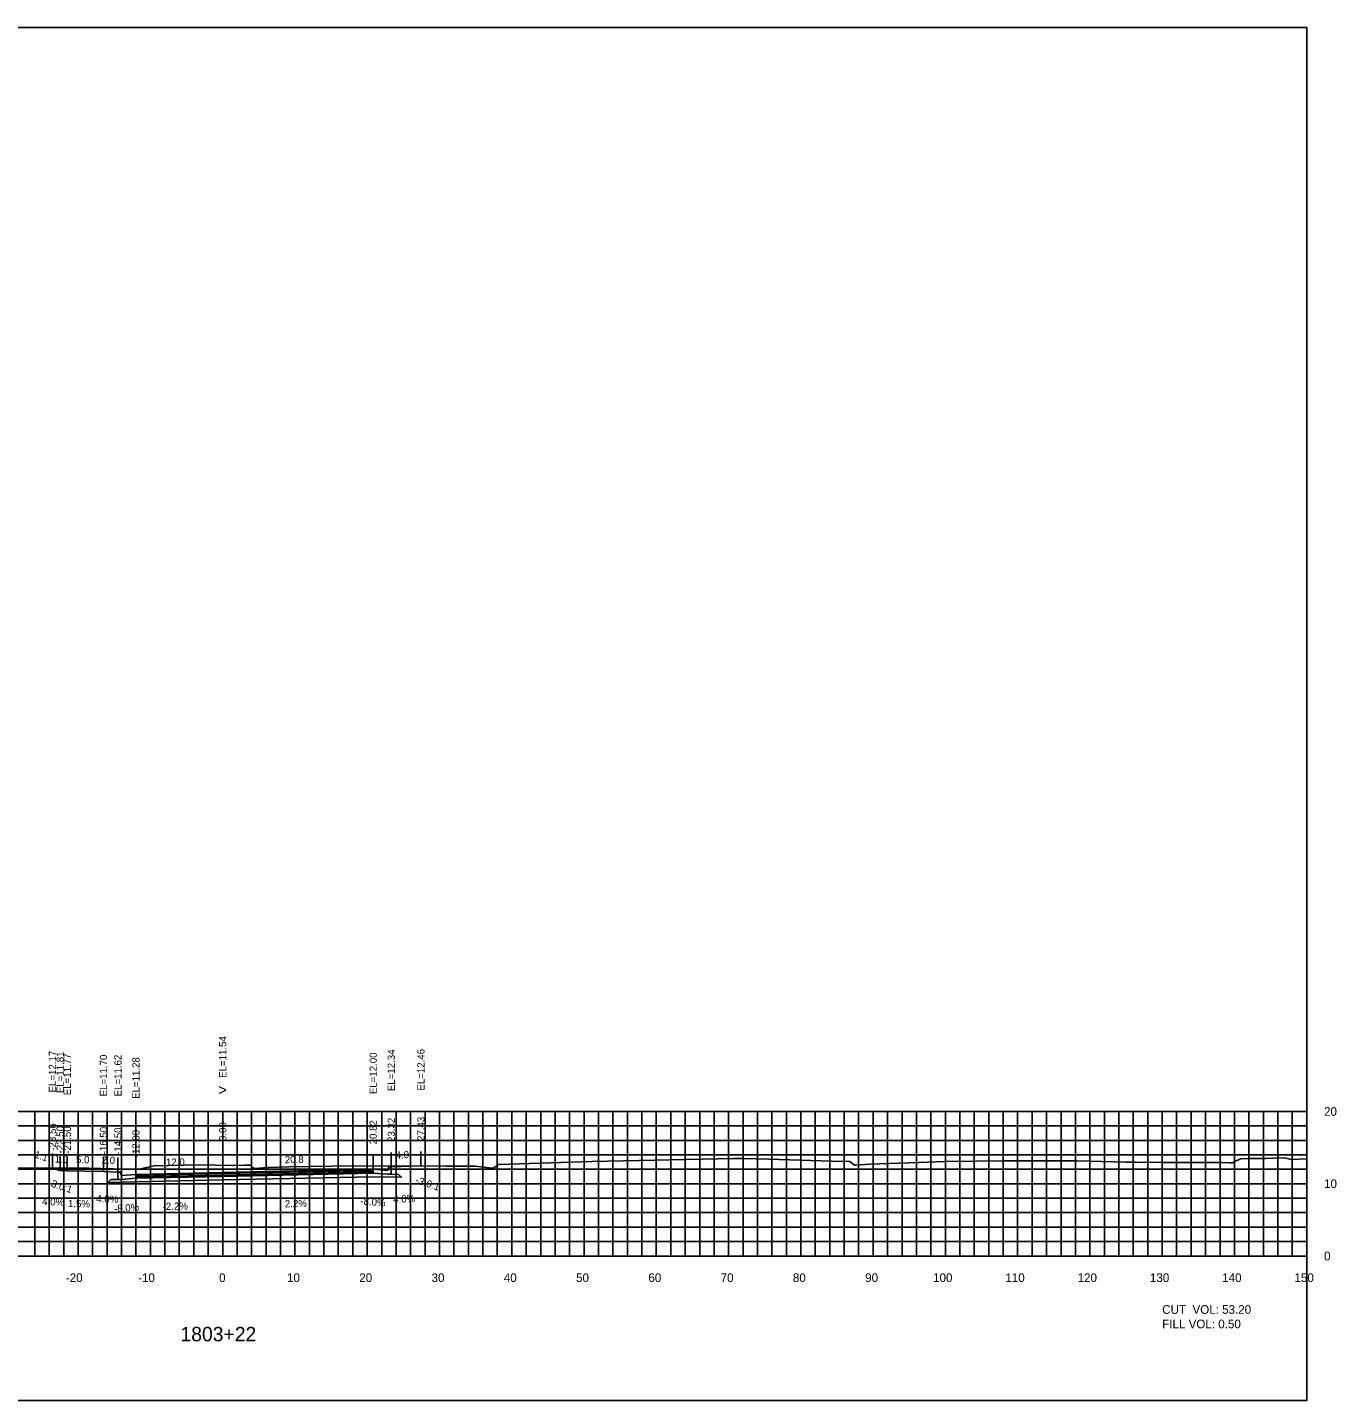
# Model space of a CAD drawing. Extents: x 1797759 to 1802785, y 249826 to 250371.
# Drawn here: x 1802604 to 1802785.1, y 250079.4 to 250269.4 of the extents above; entities that cross this region are included whole.
import ezdxf

# ---------------------------------------------------------------- set-up
doc = ezdxf.new("R2010")
doc.units = 0
for name, color, linetype in [('29', 7, 'Continuous'), ('AXIS', 7, 'Continuous'), ('great seal', 7, 'Continuous'), ('Level 1', 7, 'Continuous'), ('Level 10', 7, 'Continuous'), ('Level 13', 7, 'Continuous'), ('Level 15', 7, 'Continuous'), ('Level 30', 7, 'Continuous'), ('Level 40', 7, 'Continuous'), ('Level 45', 7, 'Continuous'), ('Level 63', 7, 'Continuous'), ('Level 7', 7, 'Continuous'), ('LS-SURVEY POINT', 7, 'Continuous'), ('PIPE', 7, 'Continuous'), ('TOPO', 7, 'Continuous')]:
    doc.layers.add(name, color=color, linetype=linetype)

msp = doc.modelspace()

# ---------------------------------------------------------------- linework, layer by layer
at = {"layer": '29'}
msp.add_lwpolyline([(1802619, 250110.56), (1802631, 250110.83), (1802651.82, 250111.28), (1802651.82, 250111.09), (1802631, 250110.64), (1802619, 250110.37)], close=True, dxfattribs=at)
at = {"layer": 'AXIS'}
for p, q in [((1802607.44, 250111.6), (1802607.44, 250113.6)), ((1802608.5, 250111.25), (1802608.5, 250113.25)), ((1802609.5, 250111.21), (1802609.5, 250113.21)), ((1802614.5, 250111.13), (1802614.5, 250113.13)), ((1802616.5, 250111.05), (1802616.5, 250113.05)), ((1802619, 250110.71), (1802619, 250112.71)), ((1802631, 250110.98), (1802631, 250112.98)), ((1802651.82, 250111.43), (1802651.82, 250113.43)), ((1802654.32, 250111.77), (1802654.32, 250113.77)), ((1802658.43, 250111.9), (1802658.43, 250113.9))]:
    msp.add_line(p, q, dxfattribs=at)
for points in [[(1802481, 250079.43), (1802781, 250079.43), (1802781, 250269.43), (1802481, 250269.43)], [(1802619, 250110.71), (1802617, 250110.55), (1802616.83, 250111.05), (1802616.5, 250111.05), (1802616.5, 250110.02), (1802617, 250110.02), (1802619, 250110.18)], [(1802651.82, 250111.43), (1802653.82, 250111.27), (1802653.99, 250111.77), (1802654.32, 250111.77), (1802654.32, 250110.74), (1802653.82, 250110.74), (1802651.82, 250110.9)]]:
    msp.add_lwpolyline(points, close=True, dxfattribs=at)
at = {"layer": 'great seal'}
msp.add_lwpolyline([(1802588.48, 250111.61), (1802612.48, 250111.6), (1802617.52, 250111.45), (1802619.18, 250111.4), (1802619.69, 250111.51), (1802621.49, 250111.89), (1802627.66, 250112.03), (1802632.32, 250111.95), (1802634.01, 250111.98), (1802634.3, 250111.98), (1802634.8, 250111.99), (1802635.2, 250111.65), (1802635.36, 250111.52), (1802636.61, 250111.65), (1802636.99, 250111.69), (1802637.36, 250111.7), (1802640.13, 250111.75), (1802649.16, 250111.93), (1802661.91, 250111.88), (1802665.94, 250111.87), (1802667.52, 250111.7), (1802668.44, 250111.6), (1802668.65, 250111.74), (1802669.16, 250112.08), (1802682.1, 250112.52), (1802701.74, 250112.94), (1802703.07, 250112.91), (1802706.59, 250112.81), (1802715.25, 250112.57), (1802717.76, 250112.5), (1802718.38, 250112.04), (1802718.43, 250112), (1802718.62, 250112.02), (1802720.55, 250112.12), (1802727.27, 250112.37), (1802730.98, 250112.49), (1802735.32, 250112.56), (1802739.15, 250112.61), (1802743.91, 250112.61), (1802749.17, 250112.62), (1802756.04, 250112.43), (1802757.31, 250112.42), (1802760.91, 250112.39), (1802768.04, 250112.38), (1802768.3, 250112.37), (1802769.24, 250112.36), (1802770.38, 250112.34), (1802770.75, 250112.33), (1802770.94, 250112.44), (1802771.82, 250112.88), (1802773.1, 250112.91), (1802775.32, 250112.93), (1802776.31, 250112.96), (1802777.93, 250113.01), (1802778.84, 250112.8), (1802781, 250112.9)], dxfattribs=at)
at = {"layer": 'Level 1'}
msp.add_lwpolyline([(1802607.44, 250111.6), (1802608.5, 250111.25), (1802609.5, 250111.21), (1802614.5, 250111.13), (1802616.5, 250111.05), (1802616.83, 250111.05), (1802617, 250110.55), (1802619, 250110.71), (1802631, 250110.98), (1802651.82, 250111.43), (1802653.82, 250111.27), (1802653.99, 250111.77), (1802654.32, 250111.77), (1802658.32, 250111.93), (1802658.43, 250111.9)], dxfattribs=at)
at = {"layer": 'Level 13'}
msp.add_lwpolyline([(1802651.82, 250110.4), (1802655.72, 250110.32), (1802655.32, 250110.72), (1802654.32, 250110.74), (1802653.82, 250110.74), (1802651.82, 250110.9), (1802631, 250110.45), (1802619, 250110.18), (1802617, 250110.02), (1802616.5, 250110.02), (1802615.5, 250110), (1802615.1, 250109.6), (1802619, 250109.68), (1802631, 250109.95)], close=True, dxfattribs=at)
at = {"layer": 'Level 15'}
for p, q in [((1802481, 250119.43), (1802781, 250119.43)), ((1802605, 250099.43), (1802605, 250119.43)), ((1802607, 250099.43), (1802607, 250119.43)), ((1802609, 250099.43), (1802609, 250119.43)), ((1802611, 250099.43), (1802611, 250119.43)), ((1802613, 250099.43), (1802613, 250119.43)), ((1802615, 250099.43), (1802615, 250119.43)), ((1802617, 250099.43), (1802617, 250119.43)), ((1802619, 250099.43), (1802619, 250119.43)), ((1802621, 250099.43), (1802621, 250119.43)), ((1802623, 250099.43), (1802623, 250119.43)), ((1802625, 250099.43), (1802625, 250119.43)), ((1802627, 250099.43), (1802627, 250119.43)), ((1802629, 250099.43), (1802629, 250119.43)), ((1802631, 250099.43), (1802631, 250119.43)), ((1802633, 250099.43), (1802633, 250119.43)), ((1802635, 250099.43), (1802635, 250119.43)), ((1802637, 250099.43), (1802637, 250119.43)), ((1802639, 250099.43), (1802639, 250119.43)), ((1802641, 250099.43), (1802641, 250119.43)), ((1802643, 250099.43), (1802643, 250119.43)), ((1802645, 250099.43), (1802645, 250119.43)), ((1802647, 250099.43), (1802647, 250119.43)), ((1802649, 250099.43), (1802649, 250119.43)), ((1802651, 250099.43), (1802651, 250119.43)), ((1802653, 250099.43), (1802653, 250119.43)), ((1802655, 250099.43), (1802655, 250119.43)), ((1802657, 250099.43), (1802657, 250119.43)), ((1802659, 250099.43), (1802659, 250119.43)), ((1802661, 250099.43), (1802661, 250119.43)), ((1802663, 250099.43), (1802663, 250119.43)), ((1802665, 250099.43), (1802665, 250119.43)), ((1802667, 250099.43), (1802667, 250119.43)), ((1802669, 250099.43), (1802669, 250119.43)), ((1802671, 250099.43), (1802671, 250119.43)), ((1802673, 250099.43), (1802673, 250119.43)), ((1802675, 250099.43), (1802675, 250119.43)), ((1802677, 250099.43), (1802677, 250119.43)), ((1802679, 250099.43), (1802679, 250119.43)), ((1802681, 250099.43), (1802681, 250119.43)), ((1802683, 250099.43), (1802683, 250119.43)), ((1802685, 250099.43), (1802685, 250119.43)), ((1802687, 250099.43), (1802687, 250119.43)), ((1802689, 250099.43), (1802689, 250119.43)), ((1802691, 250099.43), (1802691, 250119.43)), ((1802693, 250099.43), (1802693, 250119.43)), ((1802695, 250099.43), (1802695, 250119.43)), ((1802697, 250099.43), (1802697, 250119.43)), ((1802699, 250099.43), (1802699, 250119.43)), ((1802701, 250099.43), (1802701, 250119.43)), ((1802703, 250099.43), (1802703, 250119.43)), ((1802705, 250099.43), (1802705, 250119.43)), ((1802707, 250099.43), (1802707, 250119.43)), ((1802709, 250099.43), (1802709, 250119.43)), ((1802711, 250099.43), (1802711, 250119.43)), ((1802713, 250099.43), (1802713, 250119.43)), ((1802715, 250099.43), (1802715, 250119.43)), ((1802717, 250099.43), (1802717, 250119.43)), ((1802719, 250099.43), (1802719, 250119.43)), ((1802721, 250099.43), (1802721, 250119.43)), ((1802723, 250099.43), (1802723, 250119.43)), ((1802725, 250099.43), (1802725, 250119.43)), ((1802727, 250099.43), (1802727, 250119.43)), ((1802729, 250099.43), (1802729, 250119.43)), ((1802731, 250099.43), (1802731, 250119.43)), ((1802733, 250099.43), (1802733, 250119.43)), ((1802735, 250099.43), (1802735, 250119.43)), ((1802737, 250099.43), (1802737, 250119.43)), ((1802739, 250099.43), (1802739, 250119.43)), ((1802741, 250099.43), (1802741, 250119.43)), ((1802743, 250099.43), (1802743, 250119.43)), ((1802745, 250099.43), (1802745, 250119.43)), ((1802747, 250099.43), (1802747, 250119.43)), ((1802749, 250099.43), (1802749, 250119.43)), ((1802751, 250099.43), (1802751, 250119.43)), ((1802753, 250099.43), (1802753, 250119.43)), ((1802755, 250099.43), (1802755, 250119.43)), ((1802757, 250099.43), (1802757, 250119.43)), ((1802759, 250099.43), (1802759, 250119.43)), ((1802761, 250099.43), (1802761, 250119.43)), ((1802763, 250099.43), (1802763, 250119.43)), ((1802765, 250099.43), (1802765, 250119.43)), ((1802767, 250099.43), (1802767, 250119.43)), ((1802769, 250099.43), (1802769, 250119.43)), ((1802771, 250099.43), (1802771, 250119.43)), ((1802773, 250099.43), (1802773, 250119.43)), ((1802775, 250099.43), (1802775, 250119.43)), ((1802777, 250099.43), (1802777, 250119.43)), ((1802779, 250099.43), (1802779, 250119.43)), ((1802781, 250099.43), (1802781, 250119.43)), ((1802481, 250117.43), (1802781, 250117.43)), ((1802481, 250115.43), (1802781, 250115.43)), ((1802481, 250113.43), (1802781, 250113.43)), ((1802481, 250111.43), (1802781, 250111.43)), ((1802481, 250109.43), (1802781, 250109.43)), ((1802481, 250107.43), (1802781, 250107.43)), ((1802481, 250105.43), (1802781, 250105.43)), ((1802481, 250103.43), (1802781, 250103.43)), ((1802481, 250101.43), (1802781, 250101.43)), ((1802481, 250099.43), (1802781, 250099.43))]:
    msp.add_line(p, q, dxfattribs=at)
at = {"layer": 'Level 30'}
for p, q in [((1802781, 250099.43), (1802781, 250119.43)), ((1802781.06, 250119.43), (1802781, 250119.43)), ((1802781.06, 250109.43), (1802781, 250109.43)), ((1802481, 250099.43), (1802781, 250099.43)), ((1802611, 250099.37), (1802611, 250099.43)), ((1802621, 250099.37), (1802621, 250099.43)), ((1802631, 250099.37), (1802631, 250099.43)), ((1802641, 250099.37), (1802641, 250099.43)), ((1802651, 250099.37), (1802651, 250099.43)), ((1802661, 250099.37), (1802661, 250099.43)), ((1802671, 250099.37), (1802671, 250099.43)), ((1802681, 250099.37), (1802681, 250099.43)), ((1802691, 250099.37), (1802691, 250099.43)), ((1802701, 250099.37), (1802701, 250099.43)), ((1802711, 250099.37), (1802711, 250099.43)), ((1802721, 250099.37), (1802721, 250099.43)), ((1802731, 250099.37), (1802731, 250099.43)), ((1802741, 250099.37), (1802741, 250099.43)), ((1802751, 250099.37), (1802751, 250099.43)), ((1802761, 250099.37), (1802761, 250099.43)), ((1802771, 250099.37), (1802771, 250099.43)), ((1802781, 250099.37), (1802781, 250099.43)), ((1802781.06, 250099.43), (1802781, 250099.43))]:
    msp.add_line(p, q, dxfattribs=at)
at = {"layer": 'PIPE'}
msp.add_lwpolyline([(1802619, 250110.18), (1802619, 250110.37), (1802631, 250110.64), (1802651.82, 250111.09), (1802651.82, 250110.9), (1802631, 250110.45)], close=True, dxfattribs=at)
at = {"layer": 'TOPO'}
msp.add_lwpolyline([(1802651.82, 250111.28), (1802651.82, 250111.43), (1802631, 250110.98), (1802619, 250110.71), (1802619, 250110.56), (1802631, 250110.83)], close=True, dxfattribs=at)

# ---------------------------------------------------------------- texts
at = {"layer": 'AXIS'}
for s, p in [('3.0:1', (1802607.18, 250109.05)), ('-3.0:1', (1802657.58, 250109.54))]:
    msp.add_text(s, height=1, rotation=341.5651, dxfattribs=at).set_placement(p)
at = {"layer": 'Level 10'}
msp.add_text('1803+22', height=2, dxfattribs=at).set_placement((1802625.16, 250087.63))
at = {"layer": 'Level 30'}
msp.add_text('>', height=1.5, dxfattribs=at).set_placement((1802630.39, 250121.68))
at = {"layer": 'Level 40'}
for s, p in [('EL=11.54', (1802631.5, 250124.08)), ('EL=12.17', (1802607.94, 250122.07)), ('EL=11.81', (1802609, 250121.97)), ('EL=12.00', (1802652.32, 250121.83)), ('EL=12.34', (1802654.82, 250122.25)), ('EL=12.46', (1802658.93, 250122.32)), ('EL=11.77', (1802610, 250121.68)), ('EL=11.70', (1802615, 250121.53)), ('EL=11.62', (1802617, 250121.52)), ('EL=11.28', (1802619.5, 250121.18)), ('20.82', (1802652.32, 250114.88)), ('23.32', (1802654.82, 250115.22)), ('27.43', (1802658.93, 250115.35)), ('-23.56', (1802607.94, 250114.01)), ('-22.50', (1802609, 250113.62)), ('-21.50', (1802610, 250113.58)), ('-16.50', (1802615, 250113.51)), ('-14.50', (1802617, 250113.43)), ('-12.00', (1802619.5, 250113.09)), ('0.00', (1802631.5, 250115.34))]:
    msp.add_text(s, height=1, rotation=90, dxfattribs=at).set_placement(p)
at = {"layer": 'Level 45'}
for s, p in [('-20', (1802609.3, 250095.83)), ('-10', (1802619.3, 250095.83)), ('0', (1802630.5, 250095.83)), ('10', (1802639.9, 250095.83)), ('20', (1802649.9, 250095.83)), ('30', (1802659.9, 250095.83)), ('40', (1802669.9, 250095.83)), ('50', (1802679.9, 250095.83)), ('60', (1802689.9, 250095.83)), ('70', (1802699.9, 250095.83)), ('80', (1802709.9, 250095.83)), ('90', (1802719.9, 250095.83)), ('100', (1802729.3, 250095.83)), ('110', (1802739.3, 250095.83)), ('120', (1802749.3, 250095.83)), ('130', (1802759.3, 250095.83)), ('140', (1802769.3, 250095.83)), ('150', (1802779.3, 250095.83))]:
    msp.add_text(s, height=1.2, dxfattribs=at).set_placement(p)
at = {"layer": 'Level 63'}
for s, rotation, p in [('1.1', 341.5651, (1802604.87, 250113.08)), ('1.0', 357.7094, (1802607.73, 250112.38)), ('5.0', 359.1406, (1802610.7, 250112.29)), ('2.0', 357.7094, (1802614.23, 250112.24)), ('12.0', 1.2603, (1802623.16, 250111.9)), ('20.8', 1.2603, (1802639.61, 250112.27)), ('4.0', 2.2906, (1802654.95, 250112.9)), ('4.0%', 357.7094, (1802606, 250106.49)), ('1.5%', 359.1406, (1802609.58, 250106.2)), ('4.0%', 357.7094, (1802613.49, 250106.88)), ('-8.0%', 4.5739, (1802616, 250105.46)), ('-2.2%', 1.2603, (1802622.7, 250105.79)), ('2.2%', 1.2603, (1802639.61, 250106.16)), ('-8.0%', 355.4261, (1802650.02, 250106.56)), ('4.0%', 2.2906, (1802654.61, 250106.78))]:
    msp.add_text(s, height=1, rotation=rotation, dxfattribs=at).set_placement(p)
at = {"layer": 'Level 7'}
for s, p in [('20', (1802783.4, 250118.83)), ('10', (1802783.4, 250108.83)), ('0', (1802783.4, 250098.83))]:
    msp.add_text(s, height=1.2, dxfattribs=at).set_placement(p)
at = {"layer": 'LS-SURVEY POINT'}
for s, p in [('CUT  VOL: 53.20', (1802761, 250091.43)), ('FILL VOL: 0.50', (1802761, 250089.43))]:
    msp.add_text(s, height=1.2, dxfattribs=at).set_placement(p)

doc.saveas('drawing.dxf')
